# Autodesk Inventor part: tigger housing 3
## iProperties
Created: 2006-04
Part Number: tigger housing 3
Document SubType Name: Modeling
Designer: Калинин
Author: Калинин
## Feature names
1. Выдавливание1 [Extrusion]
2. Выдавливание2 [Extrusion]
3. Сопряжение1 [Fillet]
